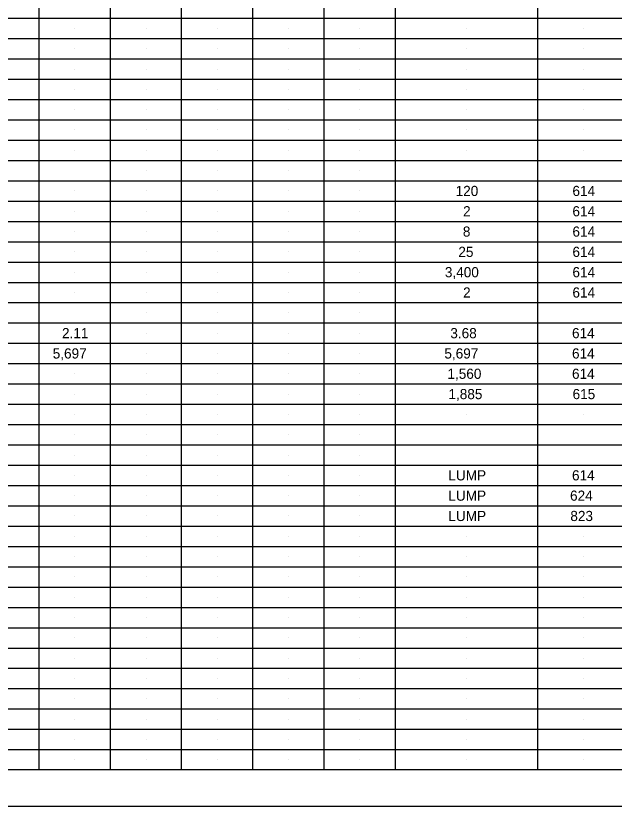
# Model space of a CAD drawing. Extents: x 1 to 35, y -2 to 20.
# Drawn here: x 9.58 to 17.83, y -1.96 to 8.94 of the extents above; entities that cross this region are included whole.
import ezdxf

# ---------------------------------------------------------------- set-up
doc = ezdxf.new("R2010")
doc.units = 0
for name, color, linetype in [('SH_Border', 7, 'Continuous'), ('SH_Cut_Line', 7, 'Continuous'), ('SH_Data', 7, 'Continuous'), ('SH_Text', 7, 'Continuous')]:
    doc.layers.add(name, color=color, linetype=linetype)

msp = doc.modelspace()

# ---------------------------------------------------------------- linework, layer by layer
at = {"layer": 'SH_Border'}
msp.add_lwpolyline([(3.031, 19.543), (34.531, 19.543), (34.531, -1.457), (3.031, -1.457)], close=True, dxfattribs=at)
at = {"layer": 'SH_Cut_Line'}
msp.add_lwpolyline([(1.031, -1.957), (35.031, -1.957), (35.031, 20.043), (1.031, 20.043)], close=True, dxfattribs=at)
at = {"layer": 'SH_Data'}
for p, q in [((14.817, -1.457), (14.817, 19.543)), ((16.781, -1.457), (16.781, 19.543)), ((9.906, -1.457), (9.906, 18.923)), ((10.888, -1.457), (10.888, 18.923)), ((11.87, -1.457), (11.87, 18.923)), ((12.852, -1.457), (12.852, 18.923)), ((13.835, -1.457), (13.835, 18.923)), ((3.031, 8.903), (33.531, 8.903)), ((10.397, 8.763), (10.397, 8.763)), ((11.379, 8.763), (11.379, 8.763)), ((12.361, 8.763), (12.361, 8.763)), ((13.343, 8.763), (13.343, 8.763)), ((14.326, 8.763), (14.326, 8.763)), ((15.799, 8.763), (15.799, 8.763)), ((15.799, 8.763), (15.799, 8.763)), ((17.406, 8.763), (17.406, 8.763)), ((3.031, 8.623), (33.531, 8.623)), ((10.397, 8.483), (10.397, 8.483)), ((11.379, 8.483), (11.379, 8.483)), ((12.361, 8.483), (12.361, 8.483)), ((13.343, 8.483), (13.343, 8.483)), ((14.326, 8.483), (14.326, 8.483)), ((15.799, 8.483), (15.799, 8.483)), ((15.799, 8.483), (15.799, 8.483)), ((17.406, 8.483), (17.406, 8.483)), ((3.031, 8.343), (33.531, 8.343)), ((10.397, 8.203), (10.397, 8.203)), ((11.379, 8.203), (11.379, 8.203)), ((12.361, 8.203), (12.361, 8.203)), ((13.343, 8.203), (13.343, 8.203)), ((14.326, 8.203), (14.326, 8.203)), ((15.799, 8.203), (15.799, 8.203)), ((15.799, 8.203), (15.799, 8.203)), ((17.406, 8.203), (17.406, 8.203)), ((3.031, 8.063), (33.531, 8.063)), ((10.397, 7.923), (10.397, 7.923)), ((11.379, 7.923), (11.379, 7.923)), ((12.361, 7.923), (12.361, 7.923)), ((13.343, 7.923), (13.343, 7.923)), ((14.326, 7.923), (14.326, 7.923)), ((15.799, 7.923), (15.799, 7.923)), ((15.799, 7.923), (15.799, 7.923)), ((17.406, 7.923), (17.406, 7.923)), ((3.031, 7.783), (33.531, 7.783)), ((10.397, 7.643), (10.397, 7.643)), ((11.379, 7.643), (11.379, 7.643)), ((12.361, 7.643), (12.361, 7.643)), ((13.343, 7.643), (13.343, 7.643)), ((14.326, 7.643), (14.326, 7.643)), ((15.799, 7.643), (15.799, 7.643)), ((15.799, 7.643), (15.799, 7.643)), ((17.406, 7.643), (17.406, 7.643)), ((3.031, 7.503), (33.531, 7.503)), ((10.397, 7.363), (10.397, 7.363)), ((11.379, 7.363), (11.379, 7.363)), ((12.361, 7.363), (12.361, 7.363)), ((13.343, 7.363), (13.343, 7.363)), ((14.326, 7.363), (14.326, 7.363)), ((15.799, 7.363), (15.799, 7.363)), ((15.799, 7.363), (15.799, 7.363)), ((17.406, 7.363), (17.406, 7.363)), ((3.031, 7.223), (33.531, 7.223)), ((10.397, 7.083), (10.397, 7.083)), ((11.379, 7.083), (11.379, 7.083)), ((12.361, 7.083), (12.361, 7.083)), ((13.343, 7.083), (13.343, 7.083)), ((14.326, 7.083), (14.326, 7.083)), ((15.799, 7.083), (15.799, 7.083)), ((15.799, 7.083), (15.799, 7.083)), ((17.406, 7.083), (17.406, 7.083)), ((3.031, 6.943), (33.531, 6.943)), ((11.379, 6.803), (11.379, 6.803)), ((12.361, 6.803), (12.361, 6.803)), ((13.343, 6.803), (13.343, 6.803)), ((14.326, 6.803), (14.326, 6.803)), ((3.031, 6.663), (33.531, 6.663)), ((10.397, 6.523), (10.397, 6.523)), ((11.379, 6.523), (11.379, 6.523)), ((12.361, 6.523), (12.361, 6.523)), ((13.343, 6.523), (13.343, 6.523)), ((14.326, 6.523), (14.326, 6.523)), ((15.799, 6.523), (15.799, 6.523)), ((15.799, 6.523), (15.799, 6.523)), ((17.406, 6.523), (17.406, 6.523)), ((3.031, 6.383), (33.531, 6.383)), ((10.397, 6.243), (10.397, 6.243)), ((10.397, 6.243), (10.397, 6.243)), ((11.379, 6.243), (11.379, 6.243)), ((12.361, 6.243), (12.361, 6.243)), ((13.343, 6.243), (13.343, 6.243)), ((14.326, 6.243), (14.326, 6.243)), ((15.799, 6.243), (15.799, 6.243)), ((15.799, 6.243), (15.799, 6.243)), ((17.406, 6.243), (17.406, 6.243)), ((3.031, 6.103), (33.531, 6.103)), ((10.397, 5.963), (10.397, 5.963)), ((11.379, 5.963), (11.379, 5.963)), ((12.361, 5.963), (12.361, 5.963)), ((13.343, 5.963), (13.343, 5.963)), ((14.326, 5.963), (14.326, 5.963)), ((3.031, 5.823), (33.531, 5.823)), ((10.397, 5.683), (10.397, 5.683)), ((11.379, 5.683), (11.379, 5.683)), ((12.361, 5.683), (12.361, 5.683)), ((13.343, 5.683), (13.343, 5.683)), ((14.326, 5.683), (14.326, 5.683)), ((15.799, 5.683), (15.799, 5.683)), ((15.799, 5.683), (15.799, 5.683)), ((17.406, 5.683), (17.406, 5.683)), ((3.031, 5.543), (33.531, 5.543)), ((10.397, 5.403), (10.397, 5.403)), ((11.379, 5.403), (11.379, 5.403)), ((12.361, 5.403), (12.361, 5.403)), ((13.343, 5.403), (13.343, 5.403)), ((14.326, 5.403), (14.326, 5.403)), ((15.799, 5.403), (15.799, 5.403)), ((15.799, 5.403), (15.799, 5.403)), ((15.799, 5.403), (15.799, 5.403)), ((15.799, 5.403), (15.799, 5.403)), ((17.406, 5.403), (17.406, 5.403)), ((17.406, 5.403), (17.406, 5.403)), ((3.031, 5.263), (33.531, 5.263)), ((10.397, 5.123), (10.397, 5.123)), ((11.379, 5.123), (11.379, 5.123)), ((12.361, 5.123), (12.361, 5.123)), ((13.343, 5.123), (13.343, 5.123)), ((14.326, 5.123), (14.326, 5.123)), ((15.799, 5.123), (15.799, 5.123)), ((15.799, 5.123), (15.799, 5.123)), ((15.799, 5.123), (15.799, 5.123)), ((15.799, 5.123), (15.799, 5.123)), ((17.406, 5.123), (17.406, 5.123)), ((17.406, 5.123), (17.406, 5.123)), ((3.031, 4.983), (33.531, 4.983)), ((11.379, 4.843), (11.379, 4.843)), ((12.361, 4.843), (12.361, 4.843)), ((13.343, 4.843), (13.343, 4.843)), ((14.326, 4.843), (14.326, 4.843)), ((3.031, 4.703), (33.531, 4.703)), ((10.397, 4.563), (10.397, 4.563)), ((11.379, 4.563), (11.379, 4.563)), ((12.361, 4.563), (12.361, 4.563)), ((13.343, 4.563), (13.343, 4.563)), ((14.326, 4.563), (14.326, 4.563)), ((3.031, 4.423), (33.531, 4.423)), ((10.397, 4.283), (10.397, 4.283)), ((10.397, 4.283), (10.397, 4.283)), ((11.379, 4.283), (11.379, 4.283)), ((12.361, 4.283), (12.361, 4.283)), ((13.343, 4.283), (13.343, 4.283)), ((14.326, 4.283), (14.326, 4.283)), ((15.799, 4.283), (15.799, 4.283)), ((15.799, 4.283), (15.799, 4.283)), ((17.406, 4.283), (17.406, 4.283)), ((3.031, 4.143), (33.531, 4.143)), ((10.397, 4.003), (10.397, 4.003)), ((11.379, 4.003), (11.379, 4.003)), ((12.361, 4.003), (12.361, 4.003)), ((13.343, 4.003), (13.343, 4.003)), ((14.326, 4.003), (14.326, 4.003)), ((15.799, 4.003), (15.799, 4.003)), ((17.406, 4.003), (17.406, 4.003)), ((3.031, 3.863), (33.531, 3.863)), ((10.397, 3.723), (10.397, 3.723)), ((11.379, 3.723), (11.379, 3.723)), ((12.361, 3.723), (12.361, 3.723)), ((13.343, 3.723), (13.343, 3.723)), ((14.326, 3.723), (14.326, 3.723)), ((15.799, 3.723), (15.799, 3.723)), ((15.799, 3.723), (15.799, 3.723)), ((15.799, 3.723), (15.799, 3.723)), ((17.406, 3.723), (17.406, 3.723)), ((17.406, 3.723), (17.406, 3.723)), ((17.406, 3.723), (17.406, 3.723)), ((3.031, 3.583), (33.531, 3.583)), ((10.397, 3.443), (10.397, 3.443)), ((11.379, 3.443), (11.379, 3.443)), ((12.361, 3.443), (12.361, 3.443)), ((13.343, 3.443), (13.343, 3.443)), ((14.326, 3.443), (14.326, 3.443)), ((15.799, 3.443), (15.799, 3.443)), ((17.406, 3.443), (17.406, 3.443)), ((3.031, 3.303), (33.531, 3.303)), ((10.397, 3.163), (10.397, 3.163)), ((11.379, 3.163), (11.379, 3.163)), ((12.361, 3.163), (12.361, 3.163)), ((13.343, 3.163), (13.343, 3.163)), ((14.326, 3.163), (14.326, 3.163)), ((3.031, 3.023), (33.531, 3.023)), ((10.397, 2.883), (10.397, 2.883)), ((11.379, 2.883), (11.379, 2.883)), ((12.361, 2.883), (12.361, 2.883)), ((13.343, 2.883), (13.343, 2.883)), ((14.326, 2.883), (14.326, 2.883)), ((3.031, 2.743), (33.531, 2.743)), ((10.397, 2.603), (10.397, 2.603)), ((11.379, 2.603), (11.379, 2.603)), ((12.361, 2.603), (12.361, 2.603)), ((13.343, 2.603), (13.343, 2.603)), ((14.326, 2.603), (14.326, 2.603)), ((15.799, 2.603), (15.799, 2.603)), ((17.406, 2.603), (17.406, 2.603)), ((3.031, 2.463), (33.531, 2.463)), ((10.397, 2.323), (10.397, 2.323)), ((11.379, 2.323), (11.379, 2.323)), ((12.361, 2.323), (12.361, 2.323)), ((13.343, 2.323), (13.343, 2.323)), ((14.326, 2.323), (14.326, 2.323)), ((15.799, 2.323), (15.799, 2.323)), ((15.799, 2.323), (15.799, 2.323)), ((15.799, 2.323), (15.799, 2.323)), ((17.406, 2.323), (17.406, 2.323)), ((17.406, 2.323), (17.406, 2.323)), ((17.406, 2.323), (17.406, 2.323)), ((3.031, 2.183), (33.531, 2.183)), ((10.397, 2.043), (10.397, 2.043)), ((11.379, 2.043), (11.379, 2.043)), ((12.361, 2.043), (12.361, 2.043)), ((13.343, 2.043), (13.343, 2.043)), ((14.326, 2.043), (14.326, 2.043)), ((15.799, 2.043), (15.799, 2.043)), ((17.406, 2.043), (17.406, 2.043)), ((3.031, 1.903), (33.531, 1.903)), ((10.397, 1.763), (10.397, 1.763)), ((10.397, 1.763), (10.397, 1.763)), ((11.379, 1.763), (11.379, 1.763)), ((11.379, 1.763), (11.379, 1.763)), ((12.361, 1.763), (12.361, 1.763)), ((12.361, 1.763), (12.361, 1.763)), ((13.343, 1.763), (13.343, 1.763)), ((13.343, 1.763), (13.343, 1.763)), ((14.326, 1.763), (14.326, 1.763)), ((14.326, 1.763), (14.326, 1.763)), ((15.799, 1.763), (15.799, 1.763)), ((15.799, 1.763), (15.799, 1.763)), ((17.406, 1.763), (17.406, 1.763)), ((17.406, 1.763), (17.406, 1.763)), ((3.031, 1.623), (33.531, 1.623)), ((10.397, 1.483), (10.397, 1.483)), ((11.379, 1.483), (11.379, 1.483)), ((12.361, 1.483), (12.361, 1.483)), ((13.343, 1.483), (13.343, 1.483)), ((14.326, 1.483), (14.326, 1.483)), ((15.799, 1.483), (15.799, 1.483)), ((17.406, 1.483), (17.406, 1.483)), ((3.031, 1.343), (33.531, 1.343)), ((10.397, 1.203), (10.397, 1.203)), ((11.379, 1.203), (11.379, 1.203)), ((12.361, 1.203), (12.361, 1.203)), ((13.343, 1.203), (13.343, 1.203)), ((14.326, 1.203), (14.326, 1.203)), ((15.799, 1.203), (15.799, 1.203)), ((17.406, 1.203), (17.406, 1.203)), ((3.031, 1.063), (33.531, 1.063)), ((10.397, 0.923), (10.397, 0.923)), ((11.379, 0.923), (11.379, 0.923)), ((12.361, 0.923), (12.361, 0.923)), ((13.343, 0.923), (13.343, 0.923)), ((14.326, 0.923), (14.326, 0.923)), ((15.799, 0.923), (15.799, 0.923)), ((17.406, 0.923), (17.406, 0.923)), ((3.031, 0.783), (33.531, 0.783)), ((10.397, 0.643), (10.397, 0.643)), ((10.397, 0.643), (10.397, 0.643)), ((11.379, 0.643), (11.379, 0.643)), ((11.379, 0.643), (11.379, 0.643)), ((12.361, 0.643), (12.361, 0.643)), ((12.361, 0.643), (12.361, 0.643)), ((13.343, 0.643), (13.343, 0.643)), ((13.343, 0.643), (13.343, 0.643)), ((14.326, 0.643), (14.326, 0.643)), ((14.326, 0.643), (14.326, 0.643)), ((15.799, 0.643), (15.799, 0.643)), ((15.799, 0.643), (15.799, 0.643)), ((17.406, 0.643), (17.406, 0.643)), ((17.406, 0.643), (17.406, 0.643)), ((3.031, 0.503), (33.531, 0.503)), ((10.397, 0.363), (10.397, 0.363)), ((11.379, 0.363), (11.379, 0.363)), ((12.361, 0.363), (12.361, 0.363)), ((13.343, 0.363), (13.343, 0.363)), ((14.326, 0.363), (14.326, 0.363)), ((15.799, 0.363), (15.799, 0.363)), ((17.406, 0.363), (17.406, 0.363)), ((3.031, 0.223), (33.531, 0.223)), ((10.397, 0.083), (10.397, 0.083)), ((11.379, 0.083), (11.379, 0.083)), ((12.361, 0.083), (12.361, 0.083)), ((13.343, 0.083), (13.343, 0.083)), ((14.326, 0.083), (14.326, 0.083)), ((15.799, 0.083), (15.799, 0.083)), ((17.406, 0.083), (17.406, 0.083)), ((3.031, -0.057), (33.531, -0.057)), ((10.397, -0.197), (10.397, -0.197)), ((11.379, -0.197), (11.379, -0.197)), ((12.361, -0.197), (12.361, -0.197)), ((13.343, -0.197), (13.343, -0.197)), ((14.326, -0.197), (14.326, -0.197)), ((15.799, -0.197), (15.799, -0.197)), ((17.406, -0.197), (17.406, -0.197)), ((3.031, -0.337), (33.531, -0.337)), ((10.397, -0.477), (10.397, -0.477)), ((11.379, -0.477), (11.379, -0.477)), ((12.361, -0.477), (12.361, -0.477)), ((13.343, -0.477), (13.343, -0.477)), ((14.326, -0.477), (14.326, -0.477)), ((15.799, -0.477), (15.799, -0.477)), ((17.406, -0.477), (17.406, -0.477)), ((3.031, -0.617), (33.531, -0.617)), ((10.397, -0.757), (10.397, -0.757)), ((11.379, -0.757), (11.379, -0.757)), ((12.361, -0.757), (12.361, -0.757)), ((13.343, -0.757), (13.343, -0.757)), ((14.326, -0.757), (14.326, -0.757)), ((15.799, -0.757), (15.799, -0.757)), ((17.406, -0.757), (17.406, -0.757)), ((3.031, -0.897), (33.531, -0.897)), ((10.397, -1.037), (10.397, -1.037)), ((11.379, -1.037), (11.379, -1.037)), ((12.361, -1.037), (12.361, -1.037)), ((13.343, -1.037), (13.343, -1.037)), ((14.326, -1.037), (14.326, -1.037)), ((15.799, -1.037), (15.799, -1.037)), ((17.406, -1.037), (17.406, -1.037)), ((3.031, -1.177), (33.531, -1.177)), ((10.397, -1.317), (10.397, -1.317)), ((11.379, -1.317), (11.379, -1.317)), ((12.361, -1.317), (12.361, -1.317)), ((13.343, -1.317), (13.343, -1.317)), ((14.326, -1.317), (14.326, -1.317)), ((15.799, -1.317), (15.799, -1.317)), ((17.406, -1.317), (17.406, -1.317))]:
    msp.add_line(p, q, dxfattribs=at)

# ---------------------------------------------------------------- texts
at = {"layer": 'SH_Text'}
for s, p in [('120', (15.648, 6.453)), ('614', (17.259, 6.453)), ('2', (15.751, 6.173)), ('614', (17.259, 6.173)), ('8', (15.748, 5.893)), ('614', (17.259, 5.893)), ('25', (15.686, 5.613)), ('614', (17.259, 5.613)), ('3,400', (15.5, 5.333)), ('614', (17.259, 5.333)), ('2', (15.751, 5.053)), ('614', (17.259, 5.053)), ('2.11', (10.22, 4.493)), ('3.68', (15.575, 4.493)), ('614', (17.253, 4.493)), ('5,697', (10.092, 4.213)), ('5,697', (15.493, 4.213)), ('614', (17.253, 4.213)), ('1,560', (15.535, 3.933)), ('614', (17.253, 3.933)), ('1,885', (15.549, 3.653)), ('615', (17.261, 3.653)), ('LUMP', (15.548, 2.533)), ('614', (17.253, 2.533)), ('LUMP', (15.548, 2.253)), ('624', (17.226, 2.253)), ('LUMP', (15.548, 1.973)), ('823', (17.23, 1.973))]:
    msp.add_text(s, height=0.14, dxfattribs=at).set_placement(p)

doc.saveas('drawing.dxf')
